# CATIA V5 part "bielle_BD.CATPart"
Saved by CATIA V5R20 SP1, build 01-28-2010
Part number: bielle_BD
Bounding box of the stored display mesh (mm): x -45 to 5, y -10 to 40, z 9.413 to 131.943
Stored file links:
  C:\Users\Matthieu\Desktop\IAO_2012_mcamard_Catia\bielle_BD.CATPart
  C:\Users\Matthieu\Desktop\IAO_Artobolevsky\Artobolevsky_786.CATProduct
  C:\Users\Matthieu\Desktop\IAO_2012_mcamard_Catia\bielle_CB.CATPart
  C:\Users\Matthieu\Desktop\IAO_2012_mcamard_Catia\skl_general.CATPart
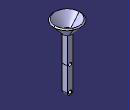
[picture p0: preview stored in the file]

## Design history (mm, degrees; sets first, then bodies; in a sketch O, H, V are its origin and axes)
Set1
  Plane1: linked copy from another document
  Point1 "B": linked copy from another document
  DatumPoint1: linked copy from another document
Body1 (main body)
  Sketch1 on Plane1, origin (0, 0, 0), H (-1, 0, 0), V (0, 0, 1)
    construction line L1 (20.4337, 14.4036) -> (20.4337, 59.4036)
    point P1 (20.4337, 14.4036)
    point P2 (20.4337, 59.4036)
    line L2 (15.4337, 14.4036) -> (15.4337, 59.4036)
    line L3 (25.4337, 59.4036) -> (25.4337, 14.4036)
    arc A1 centre (20.4337, 14.4036) radius 5 from (25.4337, 14.4036) to (15.4337, 14.4036) cw
    circle A2 centre (20.4337, 59.4036) radius 3
    circle A3 centre (20.4337, 14.4036) radius 3
    reference projected point E1 (20.4337, 14.4036) from Point1
    reference projected point E2 (20.4337, 59.4036) from DatumPoint1
    line L4 (15.4337, 59.4036) -> (15.4337, 110)
    line L5 (25.4337, 59.4036) -> (25.4337, 110)
    line L6 (25.4337, 110) -> (15.4337, 110)
    distance L1 L2 = 5
    tangency: A1 L2, A1 L3, L5 A1
    coincidence: P1 E1, E2 P2
    vertical: L4 V
    horizontal: L6 H
  Pad1: profile Sketch1, direction (0, 1, 0), length 20, opposite side length -10
  Plane2: type Offset, RefPlane face of Pad1 from Sketch1.L6, Offset 0, reversed
  Plane3: type Offset, RefPlane Plane2, Offset 20, reversed
  Sketch2 on Plane2, origin (0, 0, 110), H (1, 0, 0), V (0, -1, 0)
    circle A1 centre (-20, -15) radius 8
  Sketch3 on Plane3, origin (0, 0, 130), H (1, 0, 0), V (0, -1, 0)
    circle A1 centre (-20, -15) radius 25
    reference projected circle E1 centre (-20, -15) radius 8 from Sketch2.A1
    concentricity: E1 A1
  Fill1: Boundary Sketch2
  Blend1: StartLimit {blendlimit Curve Sketch2, Point {extremum Reference Sketch2, Direction (1, 2, 3)}}, EndLimit {blendlimit Curve Sketch3, Point {extremum Reference Sketch3, Direction (1, 2, 3)}}
  ThickSurface1: Surface Blend1, TopOffset 3, BotOffset 0
  ThickSurface2: Surface Fill1, TopOffset 3, BotOffset 0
